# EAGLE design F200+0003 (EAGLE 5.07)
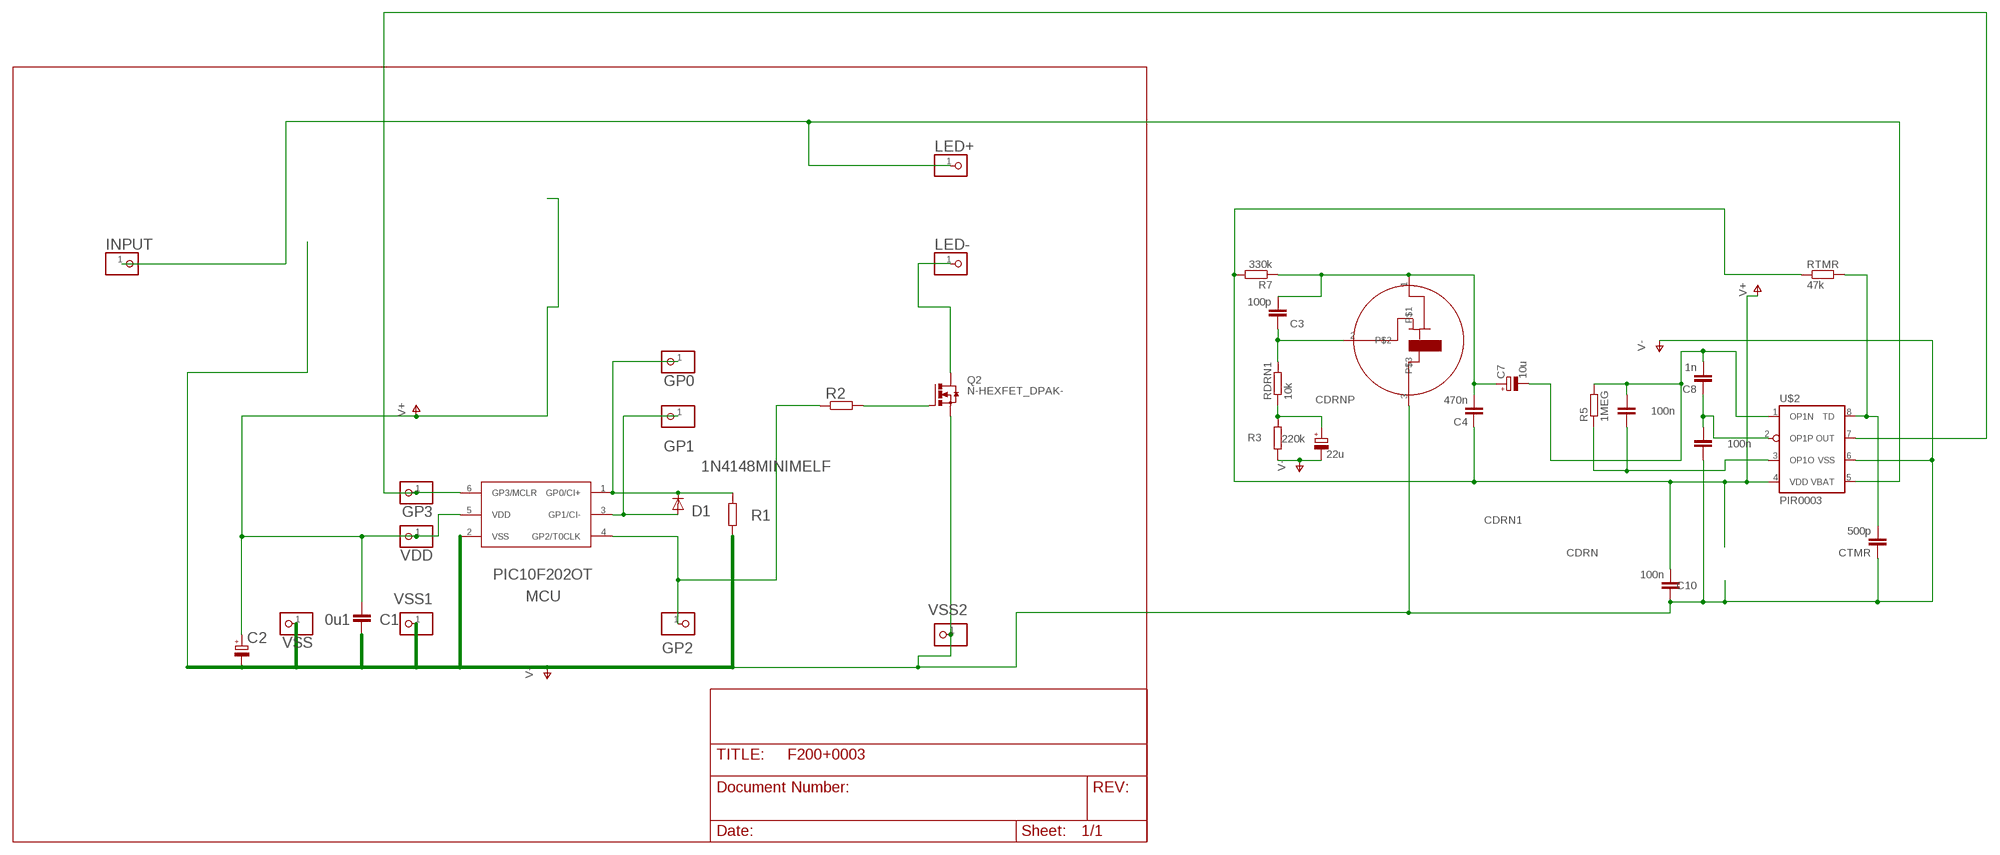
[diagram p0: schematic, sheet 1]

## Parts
C1  0u1  C-EUC1206  [C1206]
C2  CPOL-EUSMCB  [SMC_B]
C3  100p  C-EUC0805  [C0805]
C4  470n  C-EUC0805  [C0805]
C7  10u  CPOL-EUSMCA  [SMC_A]
C8  1n  C-EUC0805  [C0805]
C10  100n  C-EUC1206  [C1206]
CDRN  100n  C-EUC0805  [C0805]
CDRN1  100n  C-EUC0805  [C0805]
CDRNP  22u  CPOL-EUSMCB  [SMC_B]
CTMR  500p  C-EUC0805  [C0805]
D1  1N4148MINIMELF  [MINIMELF]
GP0  PINHD-1X1  [1X01]
GP1  PINHD-1X1  [1X01]
GP2  PINHD-1X1  [1X01]
GP3  PINHD-1X1  [1X01]
INPUT  PINHD-1X1  [1X01]
LED+  PINHD-1X1  [1X01]
LED-  PINHD-1X1  [1X01]
MCU  PIC10F202OT  [SOT23-6]
PIR  RE200B  [R200B]
Q2  N-HEXFET_DPAK-  [TO252]
R1  R-EU_R0805  [R0805]
R2  R-EU_R0805  [R0805]
R3  220k  R-EU_R0805  [R0805]
R5  1MEG  R-EU_R0805  [R0805]
R7  330k  R-EU_R0805  [R0805]
RDRN1  10k  R-EU_R0805  [R0805]
RTMR  47k  R-EU_R0805  [R0805]
U$2  PIR0003  [SO08]
VDD  PINHD-1X1  [1X01]
VSS  PINHD-1X1  [1X01]
VSS1  PINHD-1X1  [1X01]
VSS2  PINHD-1X1  [1X01]

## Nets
GP0: D1.C GP0.1 MCU.1(GP0/CI+) R1.2
GP1: D1.A GP1.1 MCU.3(GP1/CI-)
GP2: GP2.1 MCU.4(GP2/T0CLK) R2.1
GP3: GP3.1 MCU.6(GP3/MCLR) U$2.7(OUT)
HOT: LED-.1 Q2.3(D)
N$1: C3.1 PIR.2 RDRN1.2
N$3: Q2.1(G) R2.2
N$4: C3.2 C4.2 C7.+ PIR.1 R7.1
N$7: CDRNP.+ R3.2 RDRN1.1
N$8: C7.- C8.2 CDRN1.2 R5.2 U$2.1(OP1N)
N$9: C8.1 CDRN.2 U$2.2(OP1P)
N$11: CDRN1.1 R5.1 U$2.3(OP1O)
N$12: CTMR.2 RTMR.2 U$2.8(TD)
V5: INPUT.1 LED+.1 U$2.5(VBAT)
V+: C1.2 C2.+ C4.1 C10.2 MCU.5(VDD) R7.2 RTMR.1 U$2.4(VDD) VDD.1
V-: C1.1 C2.- C10.1 CDRN.1 CDRNP.- CTMR.1 MCU.2(VSS) PIR.3 Q2.2(S) R1.1 R3.1 U$2.6(VSS) VSS1.1 VSS2.1 VSS.1

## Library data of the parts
C1 C3 C4 C8 C10 CDRN CDRN1 CTMR = rcl:C-EU: CAPACITOR, European symbol
C2 = rcl-2:CPOL-EU: POLARIZED CAPACITOR, European symbol
C7 CDRNP = rcl:CPOL-EU: POLARIZED CAPACITOR, European symbol
D1 = diode-1:1N4148: DIODE
GP0 GP1-GP3 INPUT LED+ LED- VDD VSS VSS1 VSS2 = pinhead(2):PINHD-1X1: PIN HEADER
MCU = microchip-3:PIC10F2*: uPC nW 0,25/0,5k Program Flash memory Comparator
PIR = photo-elements:RE200B
Q2 = transistor-power:N-HEXFET_?-*: HEXFET® Power MOSFET
R1 R2 = rcl-2:R-EU_: RESISTOR, European symbol
R3 R5 R7 RDRN1 RTMR = rcl:R-EU_: RESISTOR, European symbol
U$2 = linear:PIR0003

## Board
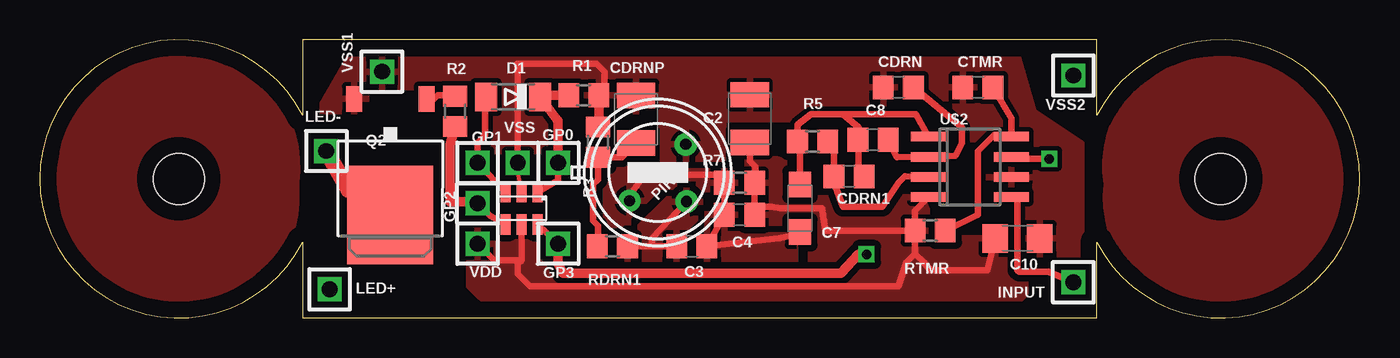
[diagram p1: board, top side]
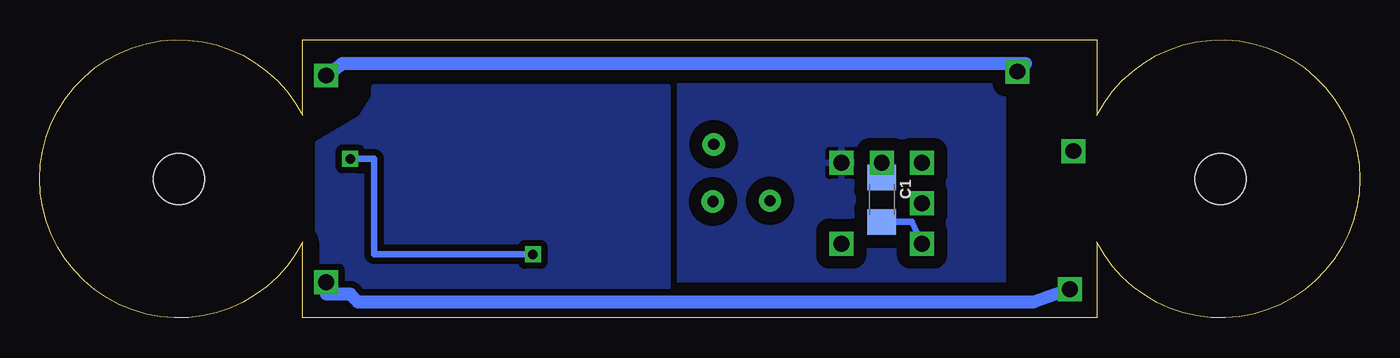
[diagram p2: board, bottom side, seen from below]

Size 83.07 x 17.5 mm. Coordinates in mm from the lower left corner, seen from the top.
Outline: 16.53,0 66.53,0 66.53,4.75 arc306 66.53,12.75 66.53,17.5 16.53,17.5 16.53,12.75 arc306 16.53,4.75 16.53,0
Copper layers (1*16): Top 0.035mm / dielectric 1.5mm / Bottom 0.035mm
Design rules "default": minimum track width 10mil, minimum drill 24mil, track to track 8mil, track to pad 8mil, pad to pad 8mil, via to via 8mil, smd to smd 8mil, copper to edge 40mil, drill to drill 8mil, minimum pad ring 10mil, minimum via ring 8mil, stop-mask expansion 4mil, vias tented up to drill 0mil, thermal gap 10mil
Holes 3.2 mm at 74.31,8.75 8.75,8.75

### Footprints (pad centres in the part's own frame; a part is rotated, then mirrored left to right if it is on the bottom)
C1206 = smd 1.6 x 1.8: 1 -1.4,0; 2 1.4,0
SMC_B = smd 1.6 x 2.4: + -1.5,0; - 1.5,0
C0805 = smd 1.3 x 1.5: 1 -0.95,0; 2 0.95,0
SMC_A = smd 1.6 x 1.4: + -1.5,0; - 1.5,0
MINIMELF = smd 1.4 x 1.8: A 1.7,0; C -1.7,0
1X01 = drill 1 pad 1.27 square: 1 0,0
SOT23-6 = smd 0.635 x 1.27: 1 -1.016,-1.016; 2 0,-1.016; 3 1.016,-1.016; 4 1.016,1.016; 5 0,1.016; 6 -1.016,1.016
R200B = drill 0.7 pad 1.4 round: 1 -2.5,0; 2 0,-2.58; 3 2.5,0
TO252 = smd 1 x 1.6: 1 -2.28,-3.53; 2 2.28,-3.53 | smd 5.4 x 6.2: 3 0,3.77
R0805 = smd 1.3 x 1.5: 1 -0.95,0; 2 0.95,0
SO08 = smd 0.6 x 2.2: 1 -1.905,-2.6; 2 -0.635,-2.6; 3 0.635,-2.6; 4 1.905,-2.6; 5 1.905,2.6; 6 0.635,2.6; 7 -0.635,2.6; 8 -1.905,2.6

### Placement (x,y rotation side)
C1  30.08,7.45 270 bottom
C2  44.68,12.54 90 top
C3  41.03,4.5 0 top
C4  44.03,6.5 180 top
C7  47.83,6.9 90 top
C8  52.43,11.2 180 top
C10  61.53,5 180 top
CDRN  54.03,14.5 0 top
CDRN1  50.93,8.9 0 top
CDRNP  37.53,12.5 90 top
CTMR  59.03,14.5 0 top
D1  29.78,13.9 180 top
GP0  32.62,9.76 0 top
GP1  27.54,9.76 0 top
GP2  27.54,7.21 90 top
GP3  32.62,4.67 0 top
INPUT  65.03,2.25 90 top
LED+  18.23,1.8 0 top
LED-  18.03,10.5 0 top
MCU  30.32,6.9 180 top
PIR  38.89,9.15 45 top
Q2  22.06,10.25 180 top
R1  34.23,14 180 top
R2  26.13,13 90 top
R3  35.13,11.06 270 top
R5  48.63,11.1 180 top
R7  44.03,8.5 0 top
RDRN1  36.03,4.5 0 top
RTMR  56.03,5.5 0 top
U$2  58.53,9.5 270 top
VDD  27.54,4.67 0 top
VSS  30.08,9.76 0 top
VSS1  21.53,15.5 90 top
VSS2  65.03,15.25 0 top

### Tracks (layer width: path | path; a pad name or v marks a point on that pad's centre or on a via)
GP0
  Top 0.406: MCU.1 32.61,8.65 32.62,8.98 GP0.1 | 32.62,12.41 32.53,12.5 | D1.C 31.58,14
  Top 0.61: GP0.1 32.62,12.41 | 32.53,12.5 D1.C | 31.58,14 R1.2
  pour Bottom (isolate 0.813): 22.46,17.14 42.78,17.14 42.78,-0.64 22.46,-0.64
GP1
  Top 0.406: MCU.3 GP1.1 27.54,11.03 28.02,11.5 28.03,11.5 28.03,13.9 D1.A
GP2
  Top 0.406: MCU.4 28.32,6.43 GP2.1 27.33,7.3
  Top 0.61: R2.1 25.83,10.9 25.83,7.3 27.33,7.3
GP3  (via drill 0.6)
  Top 0.406: GP3.1 MCU.6 | v63.53,10 61.27,10 U$2.7
  Top 0.61: GP3.1 32.62,3.41 32.93,2.8 50.43,2.8 51.53,4 v52.03,4
  Bottom 0.406: v52.03,4 62.03,4 62.03,10 v63.53,10
HOT
  Top 0.406: 19.43,8.04 Q2.3
  Top 1.016: LED-.1 19.43,8.04
N$1
  Top 0.406: RDRN1.2 38.53,4.5 | 38.53,4.5 C3.1 | PIR.2 38.53,5 38.53,4.5
  pour Top (isolate 0.406, rank 2): 36.53,5 37.03,5 40.03,8 41.53,8 41.53,6.5 40.53,5.5 40.53,4 40.03,3.5 36.53,3.5
N$2
  pour Bottom (isolate 0.406, rank 2): 43.53,14.5 62.03,14.5 62.03,13.9 62.83,12.6 65.53,11 65.53,1.5 43.53,1.5
N$3
  Top 0.406: Q2.1 24.81,13.78 25.03,14 26.08,14 R2.2
N$4
  Top 0.406: C7.+ 47.83,5.3 46.53,5 C3.2 C4.2 R7.1 42.58,9 38.03,9 36.91,7.38 PIR.1
  pour Top (isolate 0.406, rank 4): 36.03,9.5 43.53,9.5 44.53,8.5 44.53,6.5 45.53,5.5 47.53,5.5 47.53,3 42.03,3 41.53,4 41.53,6.5 40.53,7.5 39.03,7.5 37.03,5.5 35.53,5.5 35.03,6 35.03,8
N$5
  pour Top (isolate 0.406, rank 4): 67.23,8.4 arc-196 82.03,8.5 82.03,8 arc-189
  pour Top (isolate 0.406, rank 4): 1.23,8.4 arc-196 16.03,8.5 16.03,8 arc-189
N$7
  Top 0.406: CDRNP.+ 36.65,10.11 R3.2 35.13,8.7 34.83,8.4 34.83,6.1 35.13,5.8 35.13,4.55 RDRN1.1
N$8
  Top 0.406: C7.- 47.83,10.95 R5.2 47.68,12.15 48.53,12.8 50.53,12.8 | 50.53,12.8 51.53,12 51.53,11.5 | 51.53,11.5 51.53,9.25 CDRN1.2 | U$2.1 55.13,12.8 50.53,12.8 | C8.2 51.48,11.45 51.53,11.5
N$9
  Top 0.406: C8.1 53.93,10.1 U$2.2 57.63,10.2 58.03,11 58.03,12 CDRN.2
N$11
  Top 0.406: R5.1 49.98,10.7 CDRN1.1 49.98,8.55 50.53,7 53.03,7 54.03,8.5 54.43,8.9 U$2.3
N$12
  Top 0.406: RTMR.2 59.03,6.5 59.03,10.5 60.03,11.5 U$2.8 61.13,12.55 CTMR.2
V5
  Top 0.406: U$2.5 61.53,7.59 61.53,3 61.63,2.9 63.47,2.9 INPUT.1
  Bottom 0.813: LED+.1 20.53,1 63.03,1 63.53,1.5 65.03,1.5 INPUT.1
V+
  Top 0.406: 30.31,3.63 MCU.5 | 30.31,3.63 30.08,3.4 30.08,2.77 30.85,2 54.03,2 54.53,3.5 55.08,4.05 | RTMR.1 49.43,5.5 49.23,6.89 46.63,6.89 46.03,7 45.48,7 C4.1 R7.2 45.03,8.55 45.03,9.5 44.68,9.85 C2.+ | 55.08,4.05 RTMR.1 | 30.31,3.63 28.59,3.63 VDD.1 | C10.2 59.63,3 56.03,3 55.63,3.5 55.08,4.05 | RTMR.1 55.08,6.75 U$2.4
  Bottom 0.406: C1.2 28.17,6.04 VDD.1
  pour Top (isolate 0.406, rank 3): 27.03,5.5 31.03,5.5 32.03,4.5 32.03,3 48.53,3 48.53,6 44.53,6 44.53,10.5 55.53,7.5 56.53,5 61.53,5 62.03,4 62.03,1.5 61.03,0.5 28.53,0.5 27.03,2
V-
  Top 0.254: MCU.2 30.08,9.12 VSS.1
  Top 0.406: VSS.1 30.08,15.95 30.03,16 35.03,16 35.53,15.5 35.53,14.52 R1.1 | 35.18,12.06 R3.1
  Top 0.61: R1.1 35.18,12.06
  Bottom 0.406: VSS.1 C1.1
  Bottom 0.813: VSS2.1 64.03,16 21.03,16 VSS1.1
  pour Top (isolate 0.305, rank 2): 17.53,13 19.53,16.5 61.53,16.5 62.53,13 65.53,11 65.53,4 61.03,4 61.03,8 59.03,8 57.03,10 48.53,10 48.53,12.5 43.03,12.5 43.03,10 39.03,10 39.03,13 33.03,13 33.03,10.5 25.53,10.5 25.03,14.5 20.53,14.5 20.53,13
